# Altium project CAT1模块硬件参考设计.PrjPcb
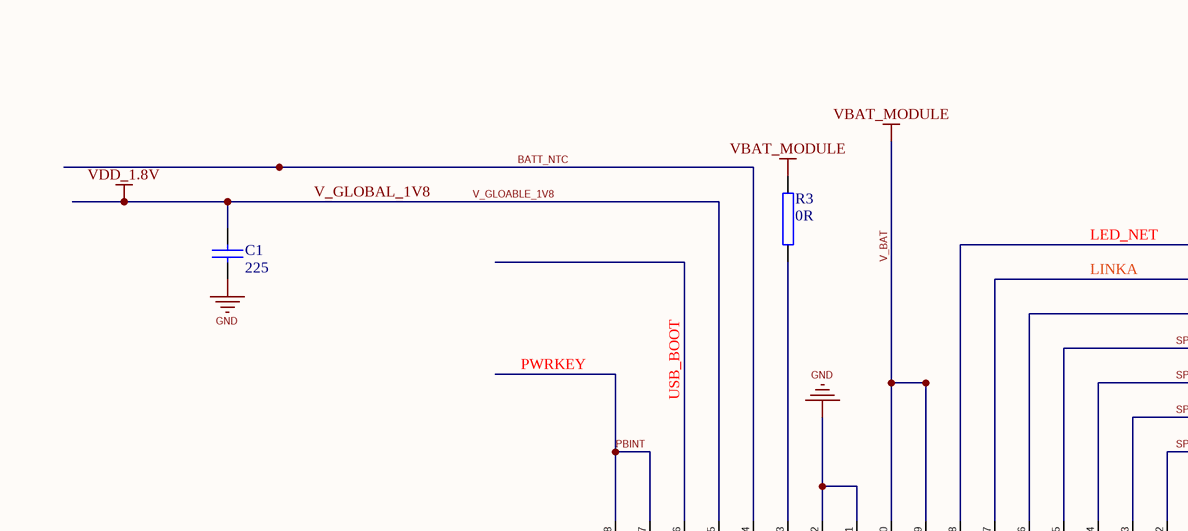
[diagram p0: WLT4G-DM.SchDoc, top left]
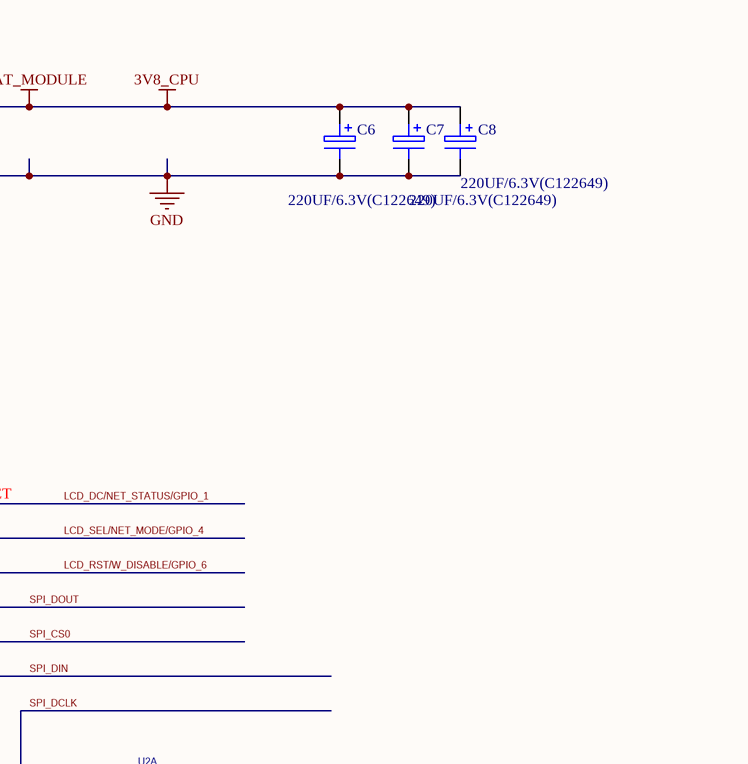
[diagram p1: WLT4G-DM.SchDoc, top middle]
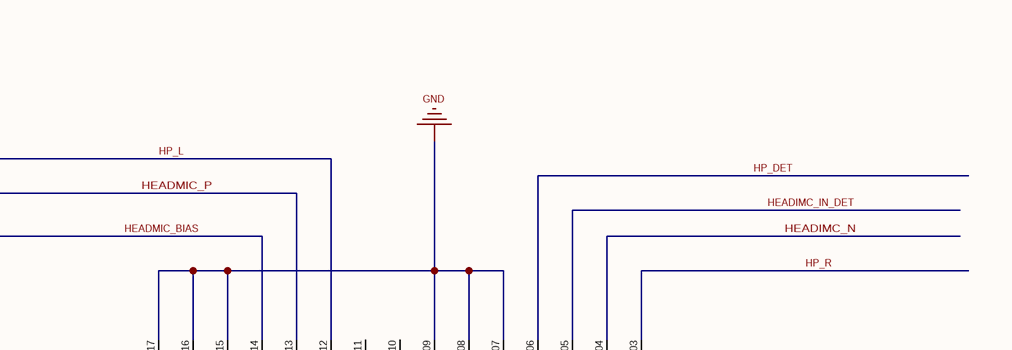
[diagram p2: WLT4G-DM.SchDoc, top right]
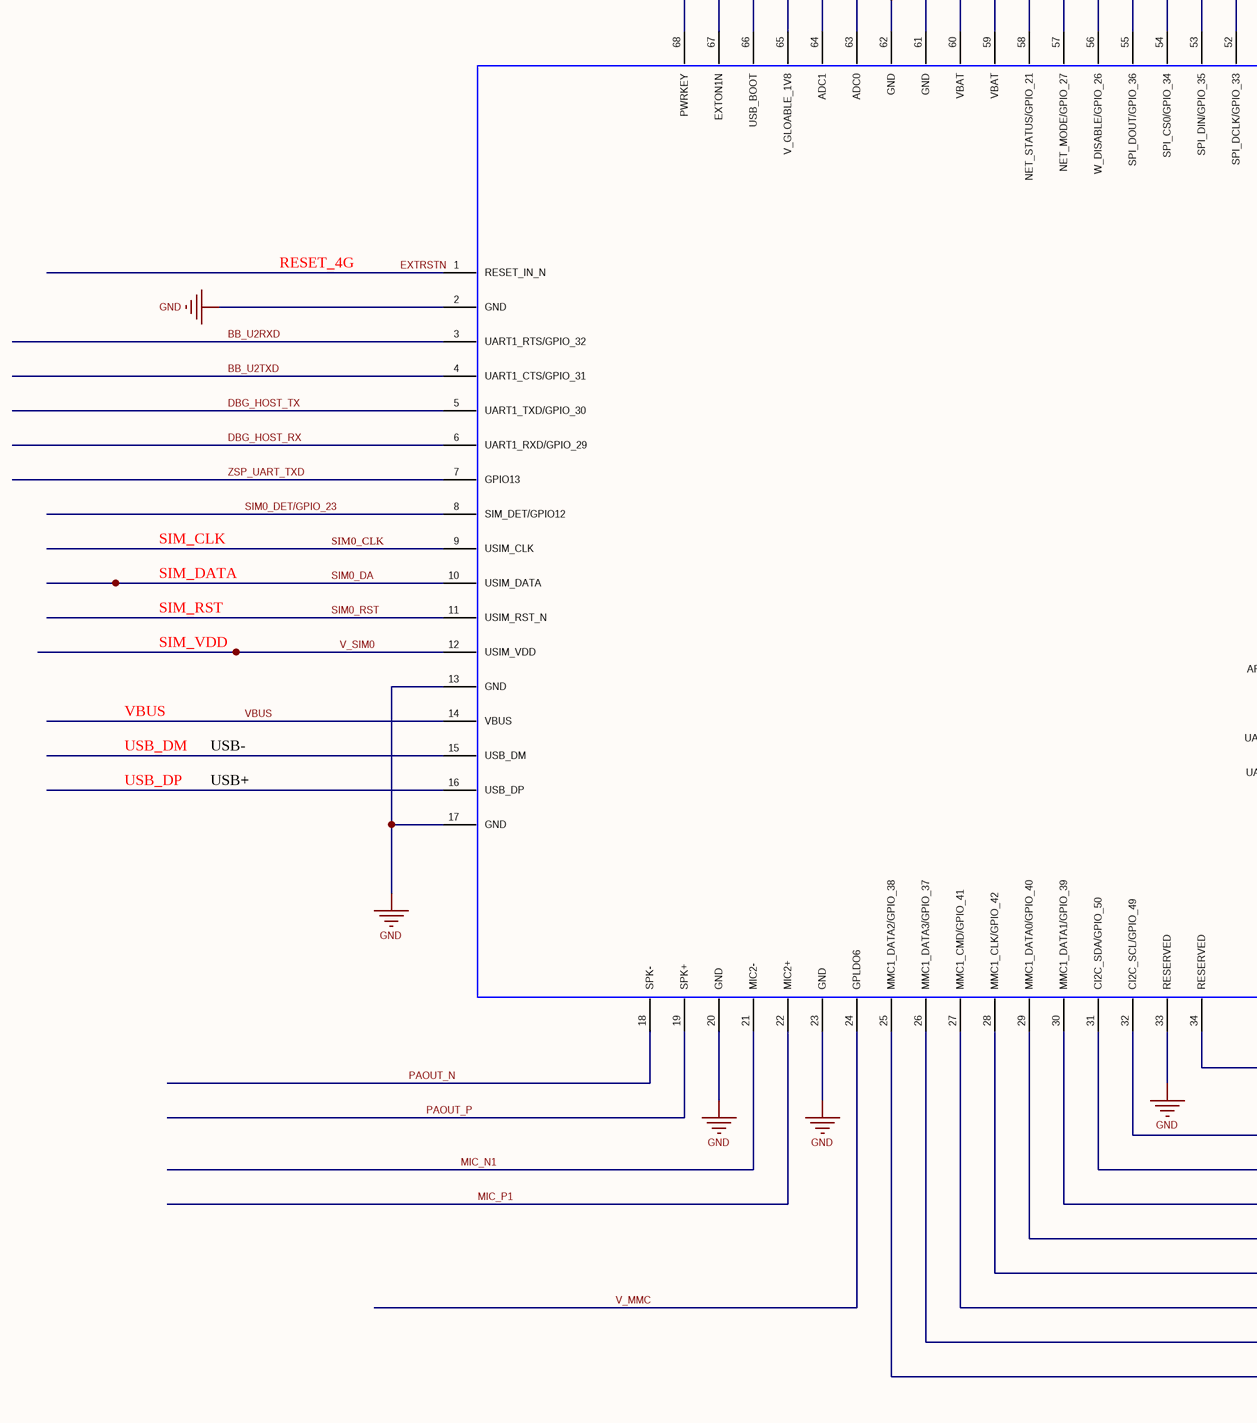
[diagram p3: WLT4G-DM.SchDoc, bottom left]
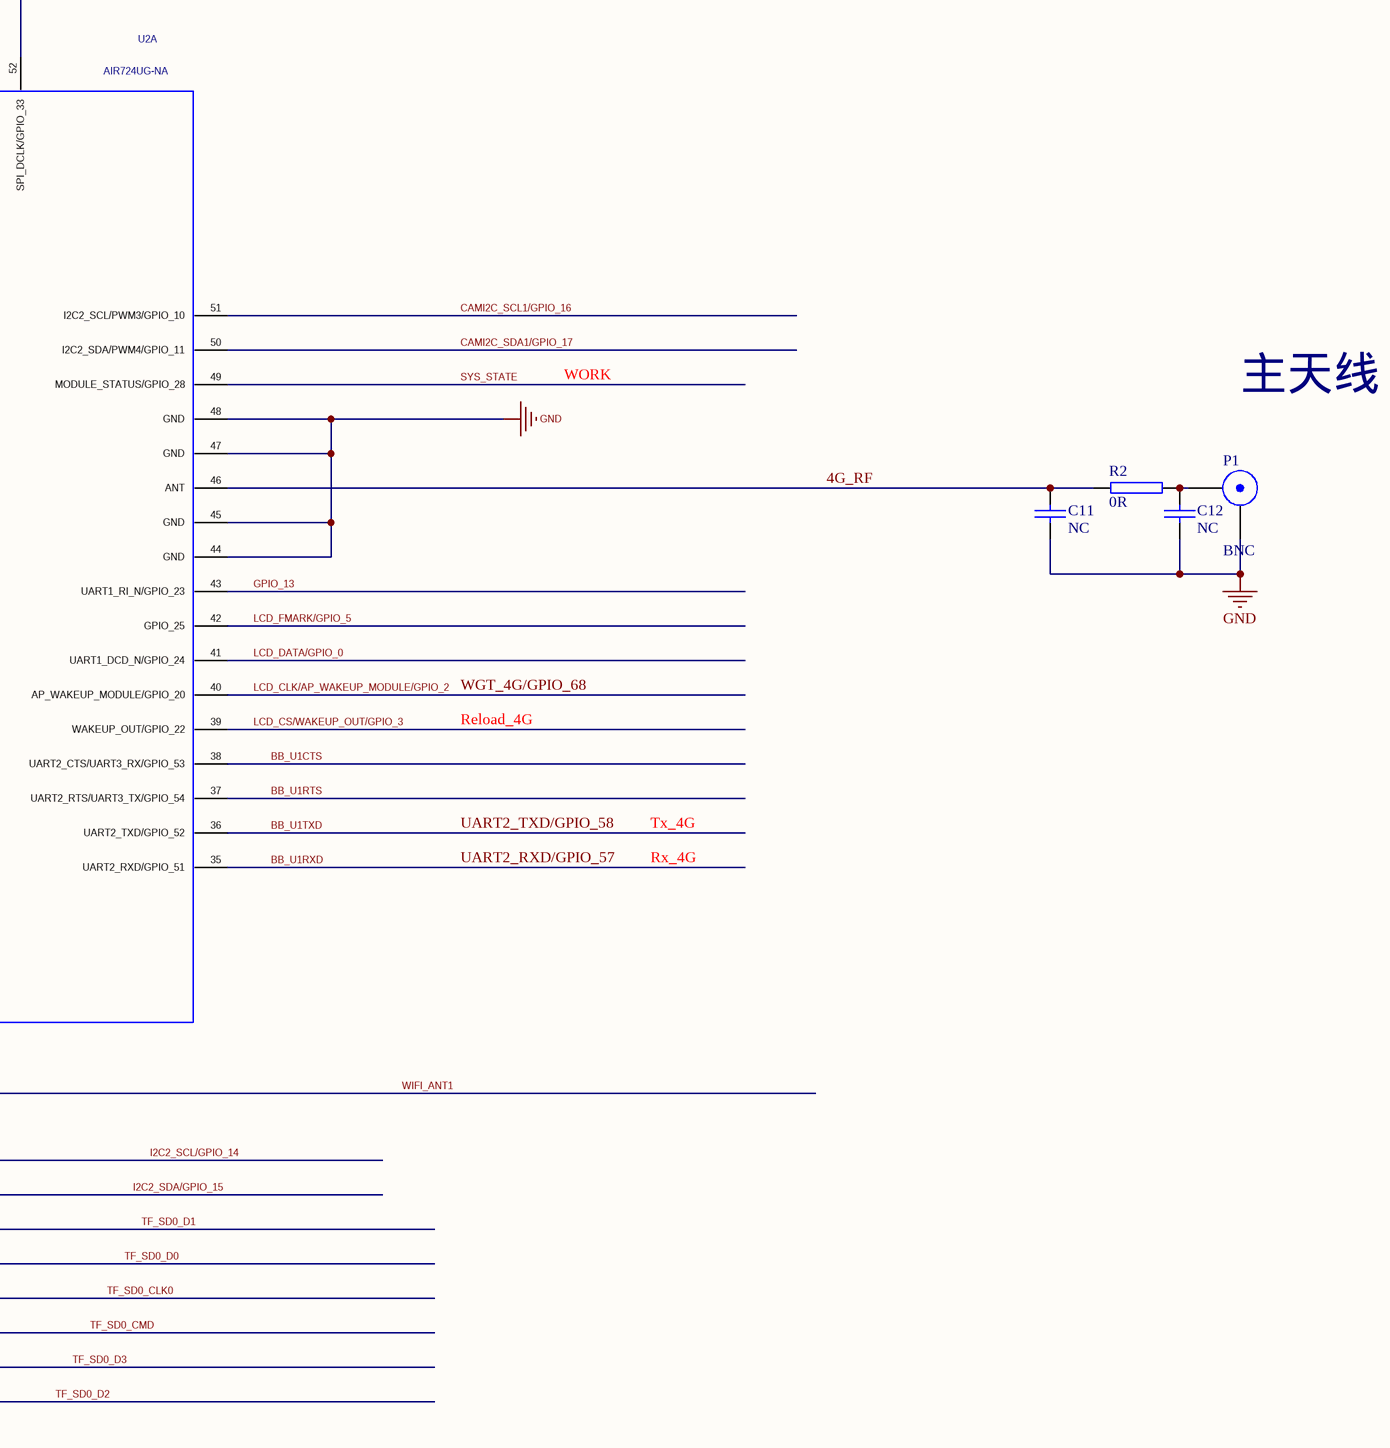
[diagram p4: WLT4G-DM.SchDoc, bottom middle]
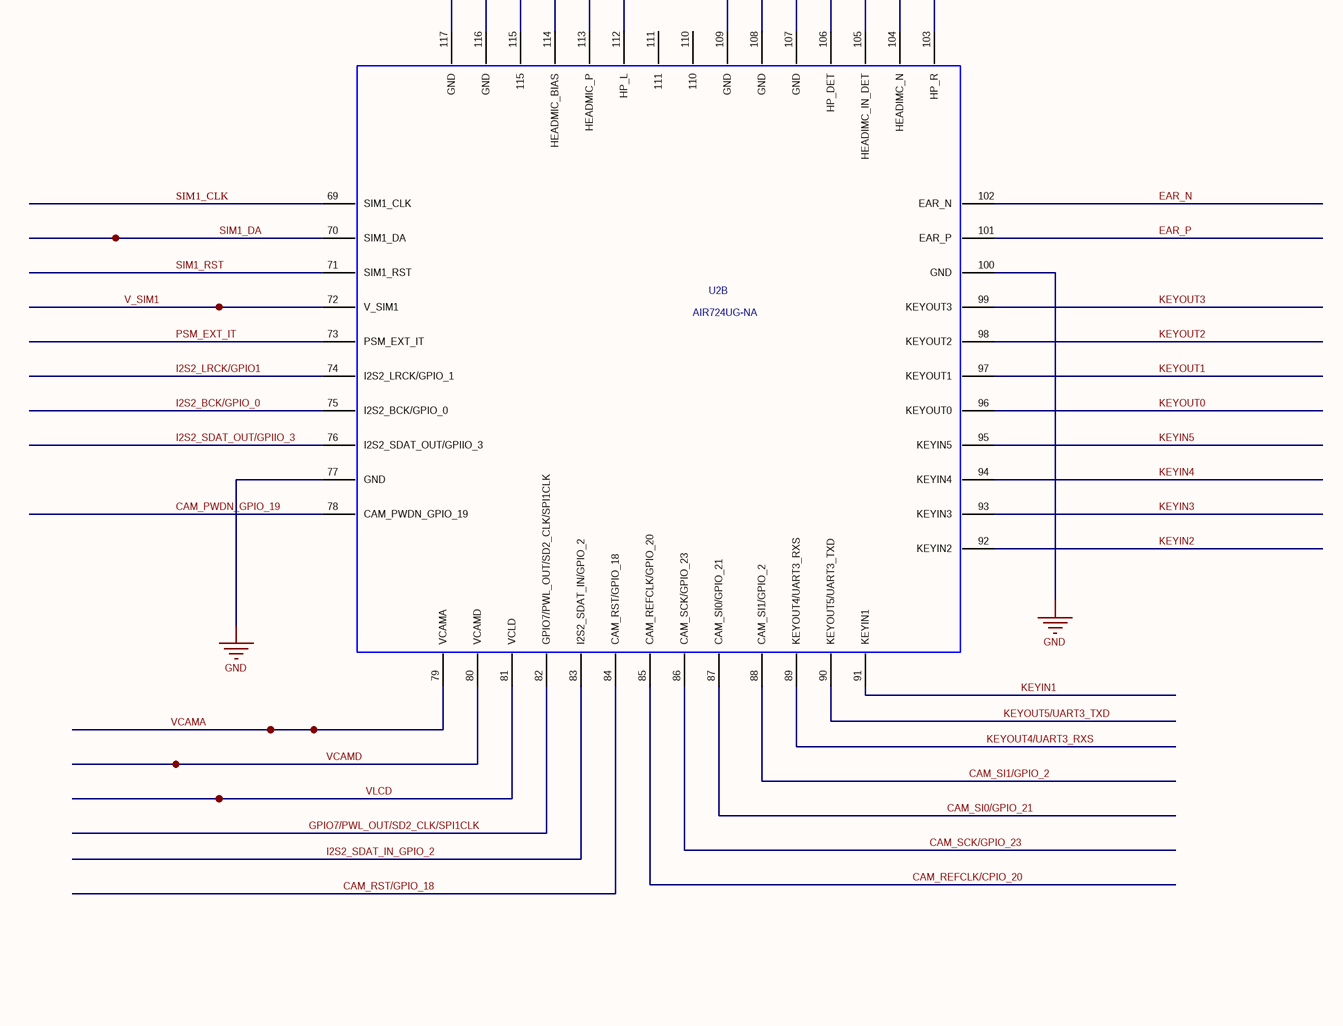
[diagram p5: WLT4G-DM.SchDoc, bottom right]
2 sheets, 43 parts. Net scope: global (net labels, ports and power ports of the same name join across sheets).
Sheets:
  WLT4G-DM.SchDoc
  cat1参考设计.SchDoc

## Sheet WLT4G-DM.SchDoc
size A0

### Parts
C1  225  [0402C]
C6  220UF/6.3V(C122649)  [CAP-B]
C7  220UF/6.3V(C122649)  [CAP-B]
C8  220UF/6.3V(C122649)  [CAP-B]
C11  NC  [0402C]
C12  NC  [0402C]
P1  BNC  [UFL]
R2  0R  [0402r]
R3  0R  [0402r]
U2  AIR724UG-NA  [AIR724]  (parts A,B of 2)

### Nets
GND: C1.1 C6.2 C7.2 C8.2 C11.2 C12.2 P1.2(Y) U2.2(GND) U2.13(GND) U2.17(GND) U2.20(GND) U2.23(GND) U2.33(RESERVED) U2.44(GND) U2.45(GND) U2.47(GND) U2.48(GND) U2.61(GND) U2.62(GND) U2.77(GND) U2.100(GND) U2.107(GND) U2.108(GND) U2.109(GND) U2.115 U2.116(GND) U2.117(GND)
V_BAT: C6.1 C7.1 C8.1 R3.2 U2.59(VBAT) U2.60(VBAT)  [also labelled 3V8_CPU, VBAT_MODULE]
V_GLOABLE_1V8: C1.2 U2.65(V_GLOABLE_1V8)  [also labelled V_GLOBAL_1V8, VDD_1.8V]
VBUS: U2.14(VBUS)
4G_RF: C11.1 R2.1 U2.46(ANT)
BATT_NTC: U2.64(ADC1)
BB_U1CTS: U2.38(UART2_CTS/UART3_RX/GPIO_53)
BB_U1RTS: U2.37(UART2_RTS/UART3_TX/GPIO_54)
BB_U1RXD: U2.35(UART2_RXD/GPIO_51)  [also labelled Rx_4G, UART2_RXD/GPIO_57]
BB_U1TXD: U2.36(UART2_TXD/GPIO_52)  [also labelled Tx_4G, UART2_TXD/GPIO_58]
BB_U2RXD: U2.3(UART1_RTS/GPIO_32)
BB_U2TXD: U2.4(UART1_CTS/GPIO_31)
CAM_PWDN_GPIO_19: U2.78(CAM_PWDN_GPIO_19)
CAM_REFCLK/CPIO_20: U2.85(CAM_REFCLK/GPIO_20)
CAM_RST/GPIO_18: U2.84(CAM_RST/GPIO_18)
CAM_SCK/GPIO_23: U2.86(CAM_SCK/GPIO_23)
CAM_SI0/GPIO_21: U2.87(CAM_SI0/GPIO_21)
CAM_SI1/GPIO_2: U2.88(CAM_SI1/GPIO_2)
CAMI2C_SCL1/GPIO_16: U2.51(I2C2_SCL/PWM3/GPIO_10)
CAMI2C_SDA1/GPIO_17: U2.50(I2C2_SDA/PWM4/GPIO_11)
DBG_HOST_RX: U2.6(UART1_RXD/GPIO_29)
DBG_HOST_TX: U2.5(UART1_TXD/GPIO_30)
EAR_N: U2.102(EAR_N)
EAR_P: U2.101(EAR_P)
EXTRSTN: U2.1(RESET_IN_N)  [also labelled RESET_4G]
GPIO7/PWL_OUT/SD2_CLK/SPI1CLK: U2.82(GPIO7/PWL_OUT/SD2_CLK/SPI1CLK)
GPIO_13: U2.43(UART1_RI_N/GPIO_23)
HEADIMC_IN_DET: U2.105(HEADIMC_IN_DET)
HEADIMC_N: U2.104(HEADIMC_N)
HEADMIC_BIAS: U2.114(HEADMIC_BIAS)
HEADMIC_P: U2.113(HEADMIC_P)
HP_DET: U2.106(HP_DET)
HP_L: U2.112(HP_L)
HP_R: U2.103(HP_R)
I2C2_SCL/GPIO_14: U2.32(CI2C_SCL/GPIO_49)
I2C2_SDA/GPIO_15: U2.31(CI2C_SDA/GPIO_50)
I2S2_BCK/GPIO_0: U2.75(I2S2_BCK/GPIO_0)
I2S2_LRCK/GPIO1: U2.74(I2S2_LRCK/GPIO_1)
I2S2_SDAT_IN_GPIO_2: U2.83(I2S2_SDAT_IN/GPIO_2)
I2S2_SDAT_OUT/GPIIO_3: U2.76(I2S2_SDAT_OUT/GPIIO_3)
KEYIN1: U2.91(KEYIN1)
KEYIN2: U2.92(KEYIN2)
KEYIN3: U2.93(KEYIN3)
KEYIN4: U2.94(KEYIN4)
KEYIN5: U2.95(KEYIN5)
KEYOUT0: U2.96(KEYOUT0)
KEYOUT1: U2.97(KEYOUT1)
KEYOUT2: U2.98(KEYOUT2)
KEYOUT3: U2.99(KEYOUT3)
KEYOUT4/UART3_RXS: U2.89(KEYOUT4/UART3_RXS)
KEYOUT5/UART3_TXD: U2.90(KEYOUT5/UART3_TXD)
LCD_CLK/AP_WAKEUP_MODULE/GPIO_2: U2.40(AP_WAKEUP_MODULE/GPIO_20)  [also labelled WGT_4G/GPIO_68]
LCD_CS/WAKEUP_OUT/GPIO_3: U2.39(WAKEUP_OUT/GPIO_22)  [also labelled Reload_4G]
LCD_DATA/GPIO_0: U2.41(UART1_DCD_N/GPIO_24)
LCD_DC/NET_STATUS/GPIO_1: U2.58(NET_STATUS/GPIO_21)  [also labelled LED_NET]
LCD_FMARK/GPIO_5: U2.42(GPIO_25)
LCD_RST/W_DISABLE/GPIO_6: U2.56(W_DISABLE/GPIO_26)
LCD_SEL/NET_MODE/GPIO_4: U2.57(NET_MODE/GPIO_27)  [also labelled LINKA]
MIC_N1: U2.21(MIC2-)
MIC_P1: U2.22(MIC2+)
PAOUT_N: U2.18(SPK-)
PAOUT_P: U2.19(SPK+)
PBINT: U2.67(EXTON1N) U2.68(PWRKEY)  [also labelled PWRKEY]
PSM_EXT_IT: U2.73(PSM_EXT_IT)
SIM0_CLK: U2.9(USIM_CLK)  [also labelled SIM_CLK]
SIM0_DA: U2.10(USIM_DATA)  [also labelled SIM_DATA]
SIM0_DET/GPIO_23: U2.8(SIM_DET/GPIO12)
SIM0_RST: U2.11(USIM_RST_N)  [also labelled SIM_RST]
SIM1_CLK: U2.69(SIM1_CLK)
SIM1_DA: U2.70(SIM1_DA)
SIM1_RST: U2.71(SIM1_RST)
SIM_VDD: U2.12(USIM_VDD)  [also labelled V_SIM0]
SPI_CS0: U2.54(SPI_CS0/GPIO_34)
SPI_DCLK: U2.52(SPI_DCLK/GPIO_33)
SPI_DIN: U2.53(SPI_DIN/GPIO_35)
SPI_DOUT: U2.55(SPI_DOUT/GPIO_36)
SYS_STATE: U2.49(MODULE_STATUS/GPIO_28)  [also labelled WORK]
TF_SD0_CLK0: U2.28(MMC1_CLK/GPIO_42)
TF_SD0_CMD: U2.27(MMC1_CMD/GPIO_41)
TF_SD0_D0: U2.29(MMC1_DATA0/GPIO_40)
TF_SD0_D1: U2.30(MMC1_DATA1/GPIO_39)
TF_SD0_D2: U2.25(MMC1_DATA2/GPIO_38)
TF_SD0_D3: U2.26(MMC1_DATA3/GPIO_37)
USB+: U2.16(USB_DP)  [also labelled USB_DP]
USB-: U2.15(USB_DM)  [also labelled USB_DM]
USB_BOOT: U2.66(USB_BOOT)
V_MMC: U2.24(GPLDO6)
V_SIM1: U2.72(V_SIM1)
VCAMA: U2.79(VCAMA)
VCAMD: U2.80(VCAMD)
VLCD: U2.81(VCLD)
WIFI_ANT1: U2.34(RESERVED)
ZSP_UART_TXD: U2.7(GPIO13)
NetC12_1: C12.1 P1.1(X) R2.2
NetR3_1: R3.1 U2.63(ADC0)

Not connected (* = marked no-connect by the designer): U2 110 111

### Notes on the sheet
- 主天线

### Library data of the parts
C1 C11 C12 = CAP: Capacitor
C6-C8 = CAP ELECTRO1: Electrolytic Capacitor
P1 = BNC: BNC Connector
R2 R3 = RES2
U2 = AIR724CG_MODULE_NEW: Air720SL; Manufacture 1: AirM2M; Geometry.Height: 2.4mm; PCB DECAL: AIR724CG_MODULE-NEW

## Sheet cat1参考设计.SchDoc
size A4
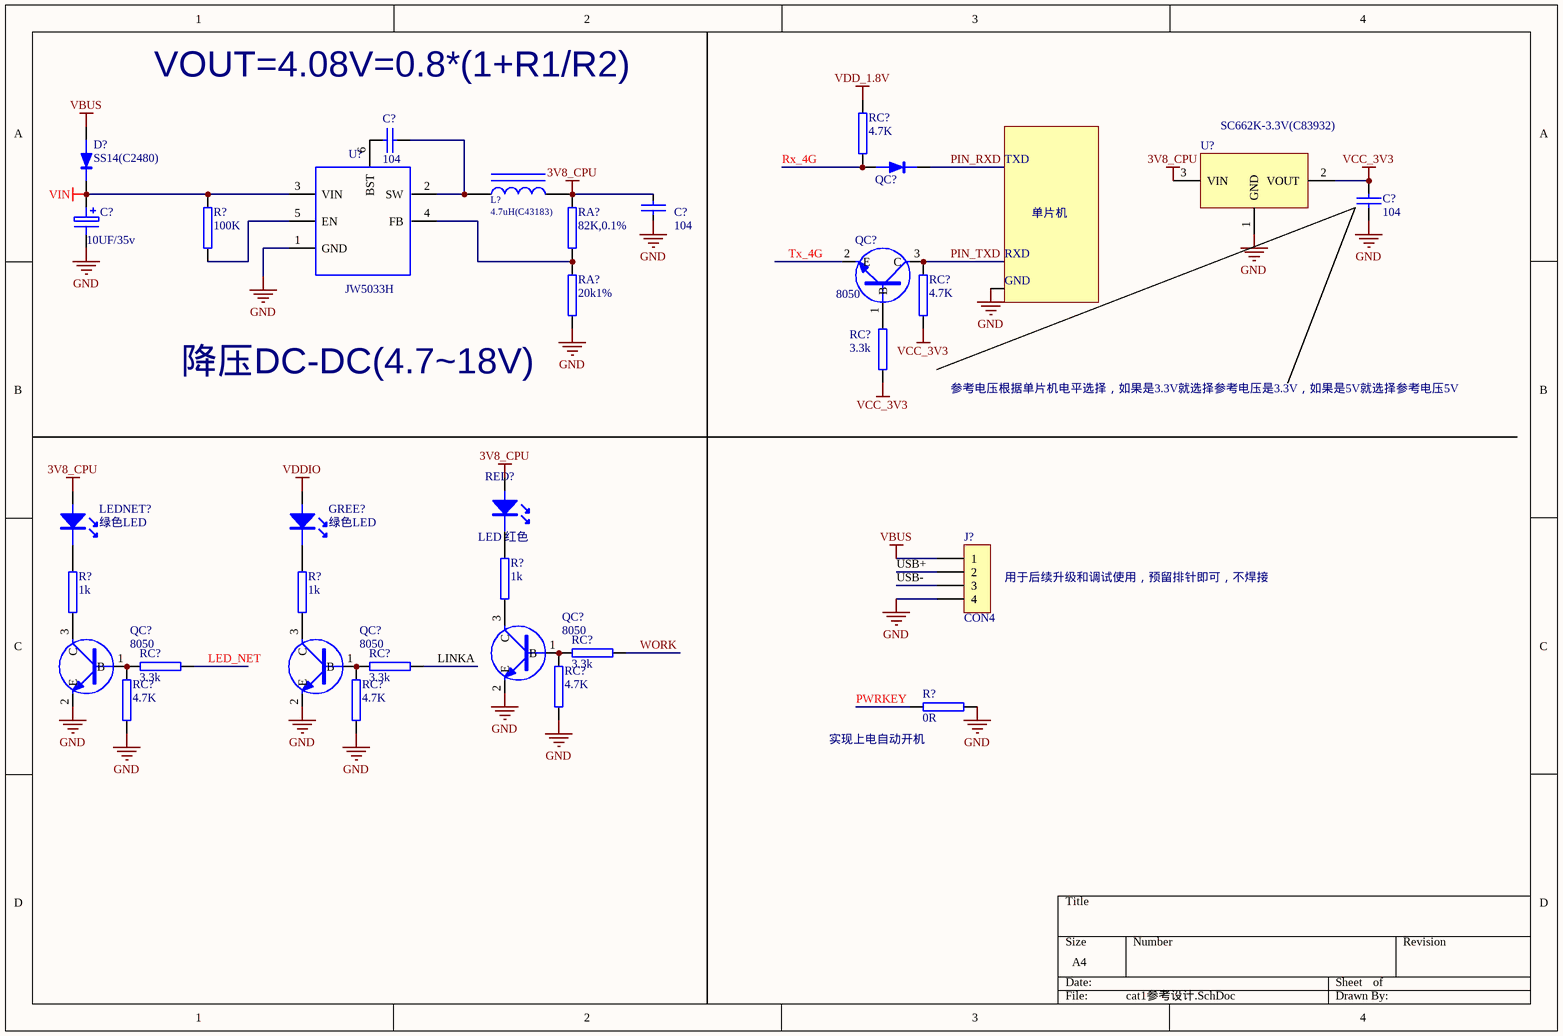
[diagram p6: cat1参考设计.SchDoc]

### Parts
(Parts that share a designator on the sheet are numbered #1, #2 ... from top to bottom, then left to right.)
C?#1  104  [0402C]
C?#2  104  [0402C]
C?#3  10UF/35v  [CAP-C]
C?#4  104  [0402C]
D?  SS14(C2480)  [1N5819S]
GREE?  绿色LED  [LED-0603]
J?  CON4  [SIP-4]
L?  4.7uH(C43183)  [L-5X5S]
LEDNET?  绿色LED  [LED-0603]
QC?#1  RB521S-30  [SOD-523]  (value not drawn)
QC?#2  8050  [SOT-23]
QC?#3  8050  [SOT-23]
QC?#4  8050  [SOT-23]
QC?#5  8050  [SOT-23]
R?#1  100K  [0603R]
R?#2  1k  [0603R]
R?#3  1k  [0603R]
R?#4  1k  [0603R]
R?#5  0R  [0603R]
RA?#1  82K,0.1%  [0603R]
RA?#2  20k1%  [0603R]
RC?#1  4.7K  [0603R]
RC?#2  3.3k  [0603R]
RC?#3  4.7K  [0603R]
RC?#4  3.3k  [0603R]
RC?#5  3.3k  [0603R]
RC?#6  3.3k  [0603R]
RC?#7  4.7K  [0603R]
RC?#8  4.7K  [0603R]
RC?#9  4.7K  [0603R]
RED?  LED 红色  [LED-0603]
U?#1  SC662K-3.3V(C83932)  [SOT-23]
U?#2  JW5033H  [SOT-23-6]

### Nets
3V8_CPU: C?#2.1 L?.2 LEDNET?.1 RA?#1.2 RED?.1 U?#1.3(VIN)  [project net V_BAT]
GND: C?#2.2 C?#3.2 C?#4.1 J?.4 QC?#3.2(E) QC?#4.2(E) QC?#5.2(E) R?#5.1 RA?#2.1 RC?#7.1 RC?#8.1 RC?#9.1 U?#1.1(GND) U?#2.1(GND)
VBUS: D?.1(K) J?.1
VCC_3V3: C?#4.2 RC?#2.2 RC?#3.1 U?#1.2(VOUT)
VDD_1.8V: RC?#1.1  [project net V_GLOABLE_1V8]
VDDIO: GREE?.1
VIN: C?#3.1 D?.2(A) R?#1.1 U?#2.3(VIN)
LED_NET: RC?#5.2  [project net LCD_DC/NET_STATUS/GPIO_1]
LINKA: RC?#6.2  [project net LCD_SEL/NET_MODE/GPIO_4]
PIN_RXD: QC?#1.2(A)
PIN_TXD: QC?#2.3(C) RC?#3.2
PWRKEY: R?#5.2  [project net PBINT]
Rx_4G: QC?#1.1(K) RC?#1.2  [project net BB_U1RXD]
Tx_4G: QC?#2.2(E)  [project net BB_U1TXD]
USB+: J?.2
USB-: J?.3
WORK: RC?#4.2  [project net SYS_STATE]
NetC?#1_1: C?#1.1 U?#2.6(BST)
NetC?#1_2: C?#1.2 L?.1 U?#2.2(SW)
NetGREE?_2: GREE?.2 R?#4.2
NetLEDNET?_2: LEDNET?.2 R?#3.2
NetQC?#2_1: QC?#2.1(B) RC?#2.1
NetQC?#3_1: QC?#3.1(B) RC?#4.1 RC?#7.2
NetQC?#3_3: QC?#3.3(C) R?#2.1
NetQC?#4_1: QC?#4.1(B) RC?#5.1 RC?#8.2
NetQC?#4_3: QC?#4.3(C) R?#3.1
NetQC?#5_1: QC?#5.1(B) RC?#6.1 RC?#9.2
NetQC?#5_3: QC?#5.3(C) R?#4.1
NetR?#1_2: R?#1.2 U?#2.5(EN)
NetR?#2_2: R?#2.2 RED?.2
NetRA?#1_1: RA?#1.1 RA?#2.2 U?#2.4(FB)

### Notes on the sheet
- VOUT=4.08V=0.8*(1+R1/R2)
- TXD
- 单片机
- RXD
- GND
- 降压DC-DC(4.7
  8V)
- 参考电压根据单片机电平选择，如果是3.3V就选择参考电压是3.3V，如果是5V就选择参考电压5V
- (near J?) 用于后续升级和调试使用，预留排针即可，不焊接
- (near R?#5) 实现上电自动开机
- Labels drawn without touching a wire or pin: GND

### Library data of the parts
C?#1 C?#4 = CAP: Capacitor
C?#2 = CAP
C?#3 = CAP ELECTRO1: Electrolytic Capacitor
D? QC?#1 = 1N5819S
GREE? LEDNET? RED? = LED
J? = CON4: Connector
L? = INDUCTOR IRON
QC?#2-QC?#5 = NPN: NPN Transistor
R?#1-R?#5 RA?#1 RA?#2 RC?#1-RC?#9 = RES2
U?#1 = SPX1117: SPX1117: SPX1117M3
U?#2 = JW5033H: Geometry.Height: 1.1mm; PCB DECAL: JW5033S

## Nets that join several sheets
GND: WLT4G-DM (27 pins), cat1参考设计 (14 pins)
V_BAT: WLT4G-DM (6 pins), cat1参考设计 (6 pins)
V_GLOABLE_1V8: WLT4G-DM (C1.2 U2.65), cat1参考设计 (RC?#1.1)
VBUS: WLT4G-DM (U2.14), cat1参考设计 (D?.1 J?.1)
BB_U1RXD: WLT4G-DM (U2.35), cat1参考设计 (QC?#1.1 RC?#1.2)
BB_U1TXD: WLT4G-DM (U2.36), cat1参考设计 (QC?#2.2)
LCD_DC/NET_STATUS/GPIO_1: WLT4G-DM (U2.58), cat1参考设计 (RC?#5.2)
LCD_SEL/NET_MODE/GPIO_4: WLT4G-DM (U2.57), cat1参考设计 (RC?#6.2)
PBINT: WLT4G-DM (U2.67 U2.68), cat1参考设计 (R?#5.2)
SYS_STATE: WLT4G-DM (U2.49), cat1参考设计 (RC?#4.2)
USB+: WLT4G-DM (U2.16), cat1参考设计 (J?.2)
USB-: WLT4G-DM (U2.15), cat1参考设计 (J?.3)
